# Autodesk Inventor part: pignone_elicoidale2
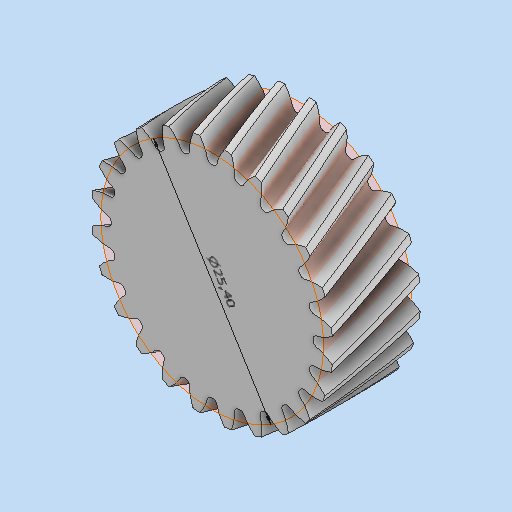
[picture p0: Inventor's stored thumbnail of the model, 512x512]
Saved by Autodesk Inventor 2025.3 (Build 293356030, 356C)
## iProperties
Created: 2025-12
Part Number: pignone_elicoidale2
Material: Generic
Document SubType Name: Modeling
Designer: R5800u
Density: 1 g/cm^3
Appearance: Default
Author: R5800u
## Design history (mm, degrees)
node "Annotazioni"
  node "Quota diametro 1" dims "d18" = 25.4 (derived)
sketch "Sketch1"
  geometry: C1 r 11.52 at (0, 0) reference; C2 r 11.908 at (0, 0) reference; C3 r 12.77 at (0, 0) reference; A1 r 13.77 centre (0, 0) between (-1.405, 13.698) and (1.405, 13.698) reference; 46 further points
  constraints: 4 centre point, 2 point on circle, 99 other
  dimensions: "d13" = 25.54027 diameter of C3 (derived)
extrude "Estrusione1" join sketch "Sketch1" distance "d0" = 10 (= Larghezza_faccia); taper "d1" = 0 deg
feature "Elicoide1" pitch "d2" = 220.44736; turns "d4" = 1; dims "d3" = 10, "d5" = 0, angle "d6" = 90 deg, angle "d7" = 90 deg, "d8" = 0, "d9" = 0
sketch "Schizzo2"
  geometry: C1 r 12.7 at (0, 0); 1 further point
  constraints: 1 centre point, 1 coincident
  dimensions: "d14" = 25.4 diameter of C1
feature "SupEstrusione1" sketch "Schizzo2" dims "d15" = 10, "d16" = 0
sketch "Schizzo3"
  geometry: 2 further points
hole "Foro1" sketch "Schizzo3" at (0, 0) diameter "d19" = 16; stored, may be unused: countersink angle "d23" = 90 deg, drill point angle "d25" = 118 deg; dims "d20" = 6, "d21" = 4, "d22" = 2, "d24" = 8
node "Solido1"
pattern_circular "Serie circolare1" dims angle "d11" = 360 deg
node "Superf1"
other parameters: "Modulo" = 1 [user parameter], "Angolo_di_pressione" = 20 deg [user parameter], "Gioco_profilo_unità" = 2.5 [user parameter], "Raggio_circolare_unità" = 3.5 [user parameter], "Diametro_testa" = 27.54027 [user parameter], "Diametro_di_fondo" = 23.04027 [user parameter], "Diametro_di_base" = 23.81618 [user parameter], "Diametro_primitivo" = 25.54027 [user parameter], "Larghezza_faccia" = 10 [user parameter; used in 1 equation term], "Angolo_elica" = 20 deg [user parameter], "Correzione_unità" = 0 [user parameter], "Modifica_aggiunta_unità" = 0 [user parameter], "Passo_circonferenziale" = 3.34321 [user parameter], "Spostamento_strumento_gioco" = 0 [user parameter], "Spostamento_strumento_totale" = 0 [user parameter], "Interno" = 0 [user parameter], "d17" = 21.2447 (derived)
